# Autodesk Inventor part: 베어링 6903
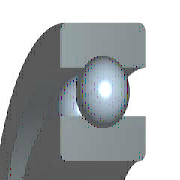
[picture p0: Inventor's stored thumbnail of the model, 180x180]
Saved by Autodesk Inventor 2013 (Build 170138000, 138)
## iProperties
Created: 2012-02
Part Number: 베어링 6903
Material: 강철, 연강
Description: 깊은 그루브 볼 베어링
Document SubType Name: Modeling
Standard: KS B 2023
Designer: mduedu
Standards Organization: KS
Language: ko-KR
Size Designation: 6003 - 17 x 35 x 10
Categories: <MemberInstance><Categories><Category DisplayName="샤프트 부품" InternalName="7f7aeb1f-a693-4053-b835-cee3144e0d98" Mnemonic="SHFT"><Category DisplayName="베어링" Inter
Density: 7.86 g/cm^3
Mass: 17.7898 g
Surface Area: 30.969 cm^2
Volume: 2.26333 cm^3
IsCustomPart: 1
Author: mduedu
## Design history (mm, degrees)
sketch "스케치" dims "d0" = 3.38 (= -0.26 x WD + 0.26 x BD)
  geometry: L1 (1.81, 11.75)-(5.19, 11.75); L2 (3.5, 11.75)-(3.5, 10.06); L3 (3.5, 11.75)-(3.5, 13.44); L4 (2.244, 10.619)-(0, 10.619); L5 (0, 8.5)-(7, 8.5); L6 (2.244, 12.881)-(0, 12.881); L7 (0, 15)-(7, 15); L8 (7, 8.5)-(7, 10.619); L9 (4.756, 10.619)-(7, 10.619); L10 (4.756, 12.881)-(7, 12.881); L11 (7, 15)-(7, 12.881); L12 (-2, 0)-(12, 0) reference; L13 (0, 7.2)-(0, 16.3) reference; 1 other entity
  constraints: 22 end point, 4 point on line, 2 collinear, 2 perpendicular, 2 symmetric about line, 1 midpoint, 1 parallel, 14 other
  dimensions: "d9" = 17 diameter of L5 L12 (= WD); "d11" = 30 diameter of L7 L12 (= BD); "d12" = 7 distance between parallel lines of L8 L13 (= KB); "d13" = 21.238 diameter of L9 L12 (= 0.326 x BD + 0.674 x WD)
revolve "본체" stored, may be unused: angle "d6" = 90 deg
revolve "볼" stored, may be unused: angle "d7" = 90 deg
pattern_circular "IDS_ARRAYBALL[SIMPL:T]" dims angle "d3" = 360 deg
body "Solid1"
fillet "모깎기1" dims "d1" = 0.3 (= KRS)
other parameters: "WD" = 17 [user parameter; used in 5 equation terms], "BD" = 30 [user parameter; used in 5 equation terms], "KB" = 7 [user parameter; used in 1 equation term], "KRS" = 0.3 [user parameter; used in 1 equation term], "d4" = 0, "d5" = 0, "d8" = 0, "d14" = 0, "d15" = 0, "BBA" = 0 [user parameter], "BC0" = 3250000 [user parameter], "BC" = 6050000 [user parameter], "BR" = 15 (= 0.5 x BD) [user parameter], "WR" = 8.5 (= 0.5 x WD) [user parameter]
